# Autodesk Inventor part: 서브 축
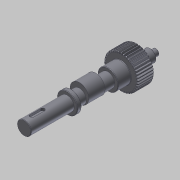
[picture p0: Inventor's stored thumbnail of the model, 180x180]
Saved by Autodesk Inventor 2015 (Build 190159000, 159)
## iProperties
Created: 2016-02
Part Number: 서브 축
Material: 강철, 연강
Document SubType Name: Modeling
Designer: mdu
Categories: <?xml version="1.0" encoding="UTF-16"?> <MemberInstance><Categories><FamilyTemplate><FamilyTemplateParameter ValueType="xs:double" Id="1" ObjectReferenceKey="da
Density: 7.86 g/cm^3
Mass: 506.173 g
Surface Area: 164.116 cm^2
Volume: 64.3986 cm^3
Appearance: 강철
CustomPartVersion: 1
Author: mdu
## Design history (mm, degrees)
sketch "Sketch1"
  geometry: C1 r 21 at (0, 0)
  constraints: 1 centre point
  dimensions: "d0" = 42 diameter of C1 (= da_da)
extrude "Extrusion1" new body sketch "Sketch1" distance "d1" = 20 (= da_b); taper "d2" = 0 deg
workplane "Work Plane2"
feature "피치 지름" dims "d4" = 10, "d5" = 0
workplane "Work Plane8"
workplane "Work Plane9"
chamfer "모따기1" distance "d49" = 1; stored, may be unused: second distance "d50" = 2, angle "d51" = 45 deg
sketch "스케치3"
  geometry: C1 r 12.5 at (0, 0); 1 further point
  constraints: 1 centre point, 1 coincident
  dimensions: "d52" = 25 diameter of C1
extrude "돌출2" join sketch "스케치3" distance "d53" = 16; taper "d54" = 0 deg
sketch "스케치4"
  geometry: C1 r 8.5 at (0, 0); 1 further point
  constraints: 1 centre point, 1 coincident
  dimensions: "d55" = 17 diameter of C1
extrude "돌출3" join sketch "스케치4" distance "d56" = 103; taper "d57" = 0 deg
sketch "스케치5"
  geometry: C1 r 7.5 at (0, 0); 1 further point
  constraints: 1 centre point, 1 coincident
  dimensions: "d62" = 15 diameter of C1
extrude "돌출4" join sketch "스케치5" distance "d63" = 16; taper "d64" = 0 deg
sketch "스케치6"
  geometry: C1 r 4 at (0, 0); 1 further point
  constraints: 1 centre point, 1 coincident
  dimensions: "d65" = 8 diameter of C1
extrude "돌출5" join sketch "스케치6" distance "d66" = 7; taper "d67" = 0 deg
chamfer "모따기2" distance "d58" = 0.5; stored, may be unused: second distance "d59" = 2, angle "d60" = 45 deg
fillet "모깎기1" dims "d61" = 0.5
feature "스퍼 기어" dims "da_b" = 20, "da_d" = 40, "da_aw" = 31, "da_da" = 42, "da_df" = 37.5, "da_dw" = 40, angle "da_beta" = 0 deg, "da_lefttooth" = 0, "da_righttooth" = 0
node "작업 평면11"
sketch "스케치7"
  geometry: C1 r 8.5 at (0, 0) reference; C2 r 11.5 at (0, 3); 1 further point
  constraints: 1 centre point, 1 tangent, 1 vertical alignment
  dimensions: "d71" = 3 distance of C2.centre point (0, 0); "d72" = 23 diameter of C2 (derived)
extrude "돌출6" join sketch "스케치7" stored distance "d73" = 20; taper "d74" = 0 deg
node "작업 평면12"
sketch "스케치8"
  geometry: C1 r 12.5 at (0, 0) reference; 1 further point
extrude "돌출7" join sketch "스케치8" distance "d76" = 5; taper "d77" = 0 deg
chamfer "모따기3" distance "d78" = 0.5; stored, may be unused: second distance "d79" = 2, angle "d80" = 45 deg
sketch "스케치9"
  geometry: L1 (-8.5, 86)-(-8.5, 138.5) reference; L2 (-8, 139)-(8, 139) reference; L3 (0, 0)-(0, 139); L4 (-8.5, 115)-(0, 115); L5 (-8.5, 115)-(-8.5, 113.5); L6 (-7, 115)-(-8.5, 113.5)
  constraints: 8 end point, 4 point on line, 1 midpoint, 1 perpendicular
  dimensions: "d81" = 24 distance between parallel lines of L2 L4; "d82" = 45 deg angle of L6 L5; "d83" = 3 diameter of L5.end L4
revolve "회전1" sketch "스케치9" stored, may be unused: angle "d84" = 90 deg
sketch "스케치10"
  geometry: L1 (-8.5, 113.5)-(-7, 115) reference; L2 (-8.5, 116.5)-(-7, 115) reference; 2 further points
  constraints: 1 coincident
node "작업점1"
node "작업 평면14"
sketch "스케치11"
  geometry: L1 (8.5, 102.5)-(-8.5, 102.5) reference; L2 (0, 102.5)-(0, -36); L3 (-2.5, 93.5)-(-2.5, 80.5); L4 (2.5, 80.5)-(2.5, 93.5); L5 (-8, 103)-(8, 103) reference; A1 r 2.5 centre (0, 93.5) between (2.5, 93.5) and (-2.5, 93.5); A2 r 2.5 centre (0, 80.5) between (-2.5, 80.5) and (2.5, 80.5)
  constraints: 6 end point, 4 point on circle, 4 tangent, 2 centre point, 1 midpoint, 1 parallel, 1 perpendicular, 1 point on line, 1 vertical alignment
  dimensions: "d85" = 7 distance edge to line of A1 L5; "d86" = 18 dimension on A2 A1; "d87" = 5 distance between parallel lines of L3 L4
extrude "돌출8" cut sketch "스케치11" distance "d88" = 3; taper "d89" = 0 deg
body "Solid1"
sketch "Sketch2"
  geometry: C1 r 21 at (0, 0) reference; C2 r 20 at (0, 0)
  constraints: 1 centre point, 1 coincident
  dimensions: "d3" = 40 diameter of C2 (= da_dw)
body "Srf1"
other parameters: "d16" = 31 (= da_aw), "d17" = 0, "d34" = 4.5 deg (computed from da_z), "d39" = 0, "d41" = 0, "d43" = 31 (= da_aw), "d46" = 31 (= da_aw), "d47" = 0, "d48" = 0, "d68" = 25
